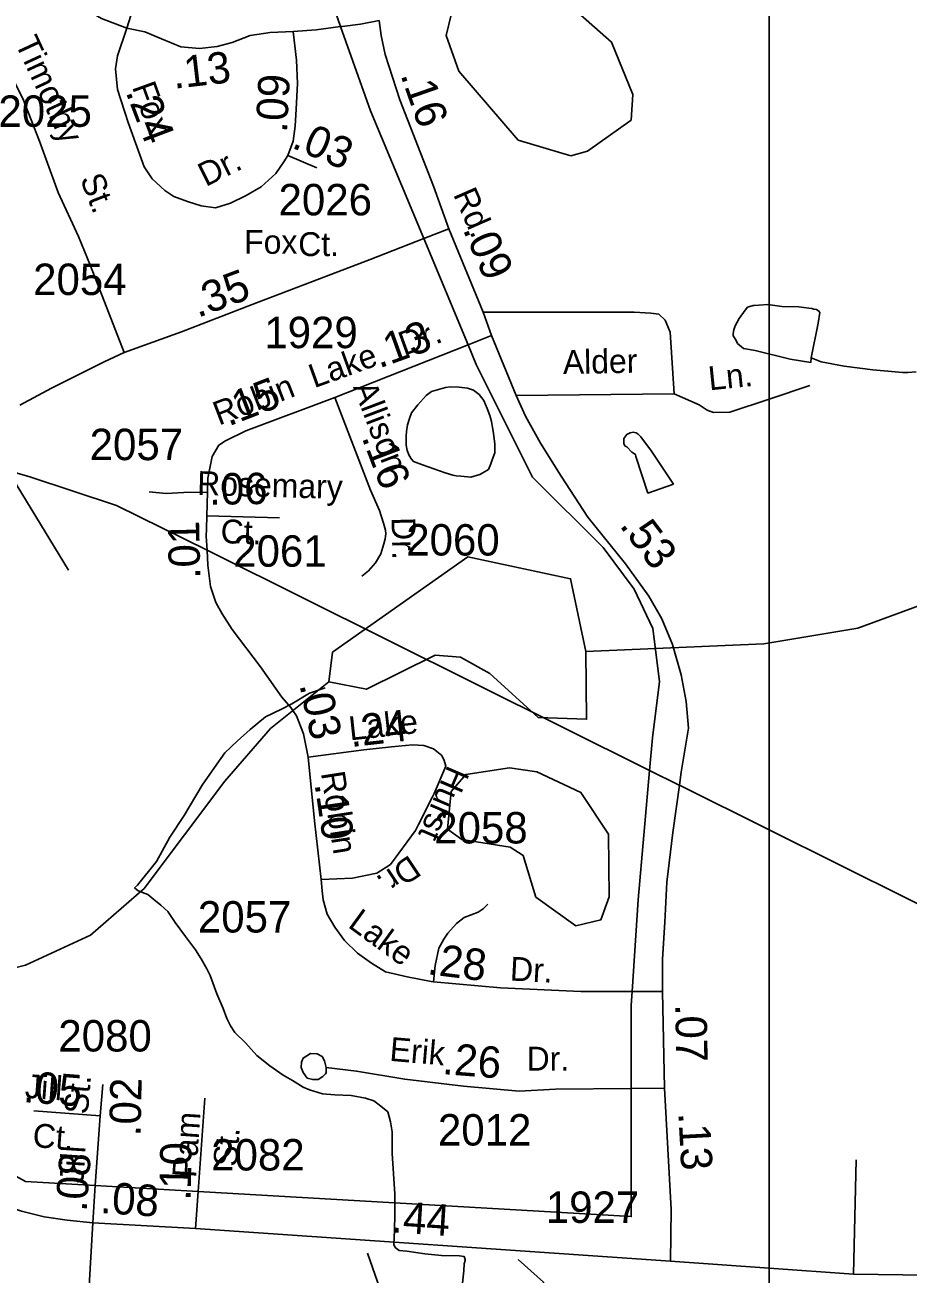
# Model space of a CAD drawing. Extents: x 2206922 to 2357709, y 510027 to 673830.
# Drawn here: x 2293330 to 2296847, y 559014 to 563987 of the extents above; entities that cross this region are included whole.
import ezdxf

# ---------------------------------------------------------------- set-up
doc = ezdxf.new("R2010")
doc.units = 0
for name, color, linetype in [('Exist Boundary Political Urban Extension UEB', 7, 'Continuous'), ('Exist Hydrographic Misc Water Feature', 7, 'Continuous'), ('Exist Hydrographic Pond Under 1500 Sq Ft', 7, 'Continuous'), ('Exist Road Non-System Type 51', 7, 'Continuous'), ('Exist Road Non-System Type 51 Label', 7, 'Continuous'), ('Exist Road Secondary Mileage Hundredths English Label', 7, 'Continuous'), ('Exist Road Secondary Type 51 Attributed', 7, 'Continuous'), ('Exist Road Secondary Type 51 Label', 7, 'Continuous'), ('Exist Road Secondary Type 51 Number Label', 7, 'Continuous'), ('Exist Utilities Electrical Transmission Line', 7, 'Continuous'), ('Map Preparation Inset Cut Line', 7, 'Continuous')]:
    doc.layers.add(name, color=color, linetype=linetype)

msp = doc.modelspace()

# ---------------------------------------------------------------- linework, layer by layer
at = {"layer": 'Exist Boundary Political Urban Extension UEB'}
for p, q in [((2295092.5, 562714.2), (2294916.3, 563137.2)), ((2293609.2, 559370.1), (2294019, 559346.2))]:
    msp.add_line(p, q, dxfattribs=at)
for points in [[(2294584.8, 563980.4), (2294564.4, 564037.5), (2294564.4, 564345.7), (2294555.3, 564400.3)], [(2294916.3, 563137.2), (2294704.6, 563645.2), (2294584.8, 563980.4)], [(2295814.2, 561021.4), (2295825.5, 561151.5), (2295853.5, 561375.6), (2295827, 561586.5), (2295753.2, 561742.1), (2295629.3, 561908), (2295349.1, 562188.2), (2295124.9, 562636.5), (2295092.5, 562714.2)], [(2295745.1, 560141.9), (2295769.5, 560507), (2295814.2, 561021.4)], [(2290079.5, 560836.9), (2290753.2, 560535), (2291902.2, 560226.8), (2292770.9, 559694.4), (2293331.4, 559386.2), (2293609.2, 559370.1)], [(2295741.4, 559756.1), (2295741.4, 560086.7), (2295745.1, 560141.9)], [(2294019, 559346.2), (2295741.4, 559246.1), (2295741.4, 559756.1)]]:
    msp.add_lwpolyline(points, dxfattribs=at)
at = {"layer": 'Exist Hydrographic Misc Water Feature'}
for points in [[(2296458, 562662.8), (2296456.4, 562644.8), (2296374, 562658), (2296233.9, 562692.4), (2296188, 562700.2), (2296180.2, 562706.2), (2296164.2, 562720), (2296157.6, 562734), (2296147.4, 562749.7), (2296147.4, 562759.8), (2296149.2, 562773.7), (2296155, 562789.9), (2296171, 562819.9), (2296194.8, 562852.1), (2296204.4, 562864.4), (2296226.5, 562870.4), (2296230.4, 562870.6), (2296248.7, 562872.7), (2296284.4, 562875), (2296340.6, 562867.4), (2296408.2, 562866.1), (2296448.6, 562860.5), (2296460.5, 562858.6), (2296468.3, 562856.7), (2296478.6, 562854.7), (2296488.2, 562848.8), (2296492.3, 562842.9), (2296484.9, 562801.1), (2296458, 562662.8)], [(2296458, 562662.8), (2296496.8, 562647.2), (2296588.3, 562630.2), (2296702.7, 562615), (2296776.7, 562607.9), (2296820.8, 562604.1), (2296842.5, 562604.5), (2296874.7, 562606.5)], [(2295185.5, 562409.2), (2295189.6, 562385), (2295193.5, 562362.9), (2295195.7, 562341.1), (2295198.4, 562321.2), (2295198.4, 562285.2), (2295188.6, 562257), (2295182.8, 562240.8), (2295173.4, 562218.8), (2295151.5, 562204.6), (2295139.8, 562198.7), (2295103.7, 562188.3), (2295063.5, 562191.9), (2295045.4, 562193.8), (2295031.3, 562195.6), (2295001.6, 562205.3), (2294910.9, 562236.4), (2294875, 562249.9), (2294866.8, 562260), (2294858.6, 562273.9), (2294850.4, 562293.8), (2294846.5, 562315.8), (2294846.1, 562351.6), (2294847.8, 562369.9), (2294851.7, 562395.7), (2294859.5, 562421.8), (2294867.5, 562444.1), (2294892.7, 562476.4), (2294926.3, 562512.6), (2294946.4, 562528.7), (2294974.3, 562537.1), (2295002.4, 562545), (2295022.3, 562547.3), (2295056.5, 562545.8), (2295090.1, 562541.9), (2295113.9, 562534.2), (2295136.5, 562516.3), (2295154.7, 562492.5), (2295168.9, 562460.7), (2295179.1, 562432.8), (2295185.5, 562409.2)], [(2295560.9, 561493.9), (2296269, 561525.5), (2296643, 561586.8), (2297108.1, 561757.8), (2298484, 562402.3)], [(2295909.3, 562159.8), (2295808, 562124.8), (2295760.3, 562270.2), (2295758.2, 562278.3), (2295744.3, 562288.1), (2295724.2, 562308.2), (2295718, 562311.9), (2295712.1, 562320.1), (2295711.9, 562325.8), (2295711.5, 562332), (2295711.5, 562342.1), (2295723.5, 562358.1), (2295737.3, 562364.2), (2295749.6, 562366.4), (2295761.7, 562364.6), (2295769.5, 562358.5), (2295779.3, 562348.5), (2295822, 562291), (2295909.3, 562159.8)], [(2293024.9, 560171.1), (2293332, 560246.8), (2293590, 560366.2), (2293804.1, 560552.1), (2294125, 560978.5), (2294306, 561188), (2294537.9, 561373.5)], [(2293765.7, 560554.4), (2293777.6, 560564.8), (2293852.9, 560659.3), (2293906, 560755.9), (2293962.8, 560842.3), (2294033.9, 560962.9), (2294082.9, 561033.4), (2294124.6, 561091.6), (2294174, 561138.1), (2294225.4, 561184.7), (2294287, 561235), (2294350.7, 561265.6), (2294390.7, 561285.9), (2294462.1, 561328.7), (2294523.6, 561349.5)], [(2295069.6, 558981.7), (2295075.2, 559030), (2295076.8, 559057.7), (2295080.9, 559071.7), (2295080.7, 559075.8), (2295076.8, 559087.7), (2295058.8, 559089.6), (2294986.8, 559091.2), (2294920.8, 559098.2), (2294848.8, 559107.9), (2294818.5, 559111.6), (2294802.7, 559123.4), (2294796.5, 559135.2), (2294799.8, 559191.1), (2294801.2, 559255.4), (2294800.4, 559337), (2294790.8, 559497), (2294790.4, 559583), (2294784.2, 559622.9), (2294773.3, 559662.6), (2294739.3, 559690.5), (2294717.2, 559706), (2294684.8, 559717.8), (2294626.7, 559727.3), (2294562.8, 559730.8), (2294512.7, 559734.3), (2294461, 559749.8), (2294436.6, 559761.6), (2294394.4, 559787), (2294356.5, 559808.5), (2294304, 559846), (2294251.9, 559887.5), (2294207, 559937.3), (2294164.9, 559978.9), (2294146.9, 560004.7), (2294132.6, 560034.5), (2294118, 560074.3), (2294093.2, 560132.1), (2294066.7, 560205.8), (2294052.4, 560231.5), (2294030, 560271.3), (2294008.1, 560307.1), (2293967.7, 560360.6), (2293926.7, 560416.2), (2293898.2, 560459.8), (2293870.3, 560485.6), (2293842, 560507.3), (2293818, 560527.1), (2293779.5, 560542.6), (2293765.7, 560554.4)]]:
    msp.add_lwpolyline(points, dxfattribs=at)
at = {"layer": 'Exist Hydrographic Pond Under 1500 Sq Ft'}
for points in [[(2295501.1, 563466.1), (2295291.9, 563529.4), (2295055.9, 563803), (2295005, 563945.1), (2295045, 564111.5), (2295177.9, 564187.5), (2295394, 564156.9), (2295663.1, 563918.7), (2295748, 563710.3), (2295741, 563608.8), (2295566.9, 563484.4), (2295501.1, 563466.1)], [(2294537.9, 561373.5), (2294552.9, 561491.3), (2295091, 561870.7), (2295500, 561783.8), (2295560.9, 561493.9)], [(2294537.9, 561373.5), (2294688, 561344.3), (2294962, 561479.8), (2295062.1, 561471.2), (2295178.9, 561406.5), (2295371.9, 561232.1), (2295564, 561224.9), (2295560.9, 561493.9)], [(2295521, 560402.7), (2295621, 560426.9), (2295654, 560518.1), (2295651, 560767.3), (2295541.1, 560933.5), (2295365.9, 561015.7), (2295257.1, 561031.1), (2295083, 561005.1), (2295024.9, 560937.4), (2295010, 560786.9), (2295068, 560746.3), (2295259.9, 560716.2), (2295311, 560682.4), (2295362, 560517.4), (2295521, 560402.7)], [(2295291.9, 559075.8), (2295393, 558985.2), (2295396.1, 558709.7), (2295255, 558624), (2295172, 558622.4), (2294963, 558695.5), (2294761, 558902.9), (2294691.9, 559101.1)]]:
    msp.add_lwpolyline(points, dxfattribs=at)
at = {"layer": 'Exist Road Non-System Type 51'}
for p, q in [((2296290.5, 562498.7), (2296451.5, 562552.3)), ((2295283.7, 562513.1), (2295912.3, 562519.2)), ((2293261.5, 562214.6), (2293502.8, 561818.4)), ((2296625.4, 559016.5), (2296636.4, 559471.8))]:
    msp.add_line(p, q, dxfattribs=at)
for points in [[(2293724.4, 562684.5), (2293590.1, 563028.5), (2293543.1, 563145.4), (2293461.1, 563320.1), (2293387.3, 563524.3), (2293321.5, 563695), (2293219.5, 563892.6)], [(2295152.1, 562844.4), (2295753.1, 562843.8), (2295819.2, 562840.4), (2295851.1, 562836.6), (2295876, 562812.1), (2295895.8, 562765.1), (2295912.3, 562519.2)], [(2295912.3, 562519.2), (2296011.6, 562476.2), (2296043.9, 562454.7), (2296069.4, 562445.3), (2296133.9, 562446.6), (2296290.5, 562498.7)], [(2294056.1, 562128.8), (2293962.1, 562126.8), (2293890.9, 562122.7), (2293823.8, 562129.5)], [(2294395.5, 561259.3), (2294387.2, 561272.1), (2294351.6, 561313.1), (2294267, 561434), (2294154.2, 561581.9), (2294113.9, 561643.7), (2294088.4, 561689.4), (2294068.2, 561752.5), (2294057.5, 561837.2), (2294053.8, 561897.9)], [(2294955.3, 560180.7), (2294961.4, 560245.1), (2294975.5, 560313.6), (2294995.6, 560349.9), (2295011.7, 560374.1), (2295046, 560412.4), (2295076.2, 560436.6), (2295132.6, 560456.7), (2295152.7, 560470.9), (2295170.9, 560489)], [(2294524.8, 559814.4), (2294514.5, 559803.8), (2294496.5, 559791.5), (2294474.5, 559791.4), (2294452.6, 559797.2), (2294436.3, 559819), (2294428.1, 559838.9), (2294429.9, 559860.9), (2294435.8, 559876.9), (2294465.6, 559895.1), (2294491.5, 559893.4), (2294511.7, 559883.6), (2294521.8, 559865.8), (2294528, 559839.9)], [(2294528, 559839.9), (2294528.2, 559817.9), (2294524.8, 559814.4)]]:
    msp.add_lwpolyline(points, dxfattribs=at)
at = {"layer": 'Exist Road Secondary Type 51 Attributed'}
for p, q in [((2294375.7, 563468.4), (2294490.9, 563418.5)), ((2295874, 559757.3), (2295865.9, 560142.3)), ((2293628.3, 559647.6), (2293639.2, 559771.5)), ((2293628.3, 559647.6), (2293364.5, 559667)), ((2294008.4, 559198.9), (2293599, 559221.6)), ((2295898.2, 559068.9), (2294008.4, 559198.9))]:
    msp.add_line(p, q, dxfattribs=at)
for points in [[(2293735.3, 563974.6), (2293767.2, 564074.8), (2293803.8, 564120.9), (2293856.3, 564164.4), (2293909, 564201.5), (2293986.7, 564249.2), (2294100.4, 564304.8), (2294252.9, 564368.4), (2294316.4, 564391.7), (2294352.2, 564400.3), (2294435, 564402.3), (2294555.3, 564400.3), (2294589.3, 564399.7), (2294718.3, 564395)], [(2293735.3, 563974.6), (2293634.5, 564012.4), (2293551.9, 564061.1), (2293497, 564128.5), (2293463.2, 564203.9), (2293416.4, 564251.8), (2293359.8, 564283.1)], [(2294375.7, 563468.4), (2294358.8, 563442.4), (2294327, 563395.8), (2294268.6, 563343), (2294209.6, 563308.9), (2294147.2, 563277.8), (2294087.7, 563259.5), (2294030.6, 563267), (2293976.3, 563284.1), (2293922, 563304.4), (2293886.5, 563328), (2293835.7, 563374.6), (2293803.9, 563423.3), (2293740.4, 563599.2), (2293698, 563730.4), (2293689.6, 563813.2), (2293697.4, 563864.5), (2293735.3, 563974.6)], [(2294396.4, 563961.2), (2294304.8, 563957.7), (2294226.1, 563945.2), (2294154.2, 563916.9), (2294094.6, 563901.9), (2294024.2, 563893.7), (2293949.3, 563899.6), (2293872.5, 563931.8), (2293806, 563959.4), (2293735.3, 563974.6)], [(2294738.4, 564005.3), (2294664.3, 563990.4), (2294591.8, 563981.3), (2294584.8, 563980.4), (2294487.9, 563967.8), (2294396.4, 563961.2)], [(2295016.4, 563176.3), (2294955.3, 563345.1), (2294821.3, 563689.1), (2294762.7, 563870.1), (2294746.3, 563944.6), (2294738.4, 564005.3)], [(2294396.4, 563961.2), (2294409.2, 563846.7), (2294413.8, 563753.9), (2294408.4, 563651.8), (2294404, 563584.5), (2294396.9, 563525.1), (2294375.7, 563468.4)], [(2293309.4, 562474.2), (2293435.6, 562542.7), (2293645.1, 562646.2), (2293724.4, 562684.5), (2293952.7, 562766.4), (2294233.4, 562875.3), (2294703.5, 563054), (2294916.3, 563137.2), (2295016.4, 563176.3)], [(2295185.7, 562751), (2295152.1, 562844.4), (2295016.4, 563176.3)], [(2295185.7, 562751), (2295092.5, 562714.2), (2294562.5, 562505.1)], [(2295865.9, 560142.3), (2295865.4, 560270.2), (2295875.5, 560417), (2295882.7, 560576), (2295906.6, 560774.2), (2295932.9, 560962.3), (2295940.2, 561014.5), (2295968.7, 561188.8), (2295960.6, 561295), (2295940.5, 561401.1), (2295905.5, 561522.1), (2295863.9, 561624.2), (2295811.5, 561714.2), (2295718.9, 561843.2), (2295568.4, 562028.7), (2295462.3, 562191.3), (2295380.4, 562323), (2295321.3, 562430.5), (2295283.7, 562513.1), (2295185.7, 562751)], [(2294562.5, 562505.1), (2294207.9, 562372), (2294126.8, 562332.6), (2294101.2, 562315.6), (2294073.6, 562269.9), (2294057.5, 562184.6), (2294056.1, 562128.8), (2294053.4, 562034.7)], [(2294562.5, 562505.1), (2294704.8, 562136.9), (2294739.8, 562054.9), (2294755.9, 562005.2), (2294763.2, 561976.6), (2294764.9, 561962.3), (2294762.6, 561942), (2294757.2, 561923.2), (2294745.8, 561883.4), (2294724.2, 561847.8), (2294696.2, 561814.7), (2294669.5, 561794.4)], [(2294053.4, 562034.7), (2294051.5, 561982), (2294050.5, 561953.4), (2294053.8, 561897.9)], [(2294053.4, 562034.7), (2294342.2, 562026.7)], [(2294455.7, 561074.6), (2294437.6, 561167.3), (2294409.4, 561237.8), (2294395.5, 561259.3)], [(2294455.7, 561074.6), (2294677.3, 561102.8), (2294788.1, 561114.9), (2294870.7, 561122.9), (2294917, 561120.9), (2294955.3, 561106.8), (2294987.5, 561080.6), (2294997.6, 561060.5), (2295003.7, 561038.3), (2294957.3, 560929.4), (2294950.7, 560916.3)], [(2294508.1, 560586.8), (2294481.9, 560820.6), (2294455.7, 561074.6)], [(2294950.7, 560916.3), (2294894.9, 560806.5), (2294882.8, 560782.3), (2294784.1, 560647.2), (2294729.7, 560613), (2294633, 560592.8), (2294508.1, 560586.8)], [(2293599, 559221.6), (2293496.8, 559232.4), (2293406.1, 559245.3), (2293315.4, 559267.5), (2293218.7, 559299.7), (2293041.4, 559394.5), (2292791.1, 559525.1), (2292504.6, 559688.9), (2292129.1, 559890.9), (2291851.9, 560034.6), (2291737.4, 560081.4), (2291582.9, 560142), (2291334.2, 560229.5), (2290744.7, 560432), (2289908, 560741.5)], [(2295865.9, 560142.3), (2295745.1, 560141.9), (2295541.6, 560141.3), (2295221.2, 560156.4), (2294955.3, 560180.7), (2294945.2, 560181.6), (2294850.6, 560199.7), (2294763.9, 560219.9), (2294707.5, 560254.2), (2294653.1, 560294.5), (2294600.7, 560344.9), (2294562.5, 560397.3), (2294532.2, 560449.7), (2294516.1, 560506.1), (2294512.1, 560542.4), (2294508.1, 560586.8)], [(2295874, 559757.3), (2295741.4, 559756.1), (2295440.8, 559753.3), (2295295.8, 559745.2), (2295074.2, 559765.4), (2294840.5, 559792.6), (2294649.1, 559824.8), (2294528, 559839.9)], [(2295898.2, 559068.9), (2295900.2, 559274.5), (2295874, 559757.3)], [(2294008.4, 559198.9), (2294019, 559346.2), (2294045.6, 559717.3)], [(2293599, 559221.6), (2293609.2, 559370.1), (2293628.3, 559647.6)], [(2293599, 559221.6), (2293571, 558742)], [(2298859.7, 558470.4), (2298505, 558600.3), (2298291.2, 558676.4), (2297727.2, 558892.3), (2297482.7, 558970), (2297362.4, 558994.9), (2297214.4, 559009.5), (2296625.4, 559016.5), (2296290.5, 559040.6), (2295898.2, 559068.9)]]:
    msp.add_lwpolyline(points, dxfattribs=at)
at = {"layer": 'Exist Utilities Electrical Transmission Line'}
msp.add_line((2295932.9, 560962.3), (2296290.5, 560784.4), dxfattribs=at)
for points in [[(2293261.5, 562214.6), (2293348.6, 562189.4), (2293693.6, 562074.7), (2294053.8, 561897.9)], [(2294053.8, 561897.9), (2294081.2, 561884.5), (2295814.2, 561021.4)], [(2295814.2, 561021.4), (2295932.8, 560962.4), (2295932.9, 560962.3)], [(2296290.5, 560784.4), (2298507.6, 559681.3), (2299341.4, 559256.6)]]:
    msp.add_lwpolyline(points, dxfattribs=at)
at = {"layer": 'Map Preparation Inset Cut Line'}
for p, q in [((2296290.5, 564742.9), (2296290.5, 562498.7)), ((2296290.5, 562498.7), (2296290.5, 560784.4)), ((2296290.5, 560784.4), (2296290.5, 559040.6)), ((2296290.5, 559040.6), (2296290.5, 556643.1))]:
    msp.add_line(p, q, dxfattribs=at)

# ---------------------------------------------------------------- texts
at = {"layer": 'Exist Road Non-System Type 51 Label'}
for s, rotation, p in [('Timothy', 294.9543, (2293288.2, 563916.2)), ('St.', 291.342, (2293547.5, 563374.7)), ('Alder', 1.1146, (2295470.2, 562597.9)), ('Ln.', 5.8419, (2296052.7, 562533.2)), ('Jill', 355.7903, (2293327.4, 559719.1)), ('St.', 84.9728, (2293579.2, 559651.1)), ('Pam', 85.983, (2294010.1, 559398.6)), ('Ct.', 355.7903, (2293357.6, 559522.9)), ('St.', 85.983, (2294173.4, 559443)), ('Jill', 86.2873, (2293561.5, 559377.2))]:
    msp.add_text(s, height=95, rotation=rotation, dxfattribs=at).set_placement(p)
at = {"layer": 'Exist Road Secondary Mileage Hundredths English Label'}
for s, rotation, p in [('.13', 6.5815, (2293922.6, 563733)), ('.09', 86.9683, (2294371.7, 563556.6)), ('.16', 289.2316, (2294822.4, 563788.9)), ('.24', 290.84, (2293728.9, 563721.1)), ('.03', 336.5606, (2294386.1, 563500.6)), ('.09', 293.502, (2295070, 563174.2)), ('.35', 20.4497, (2294017.1, 562821.1)), ('.13', 19.825, (2294738.5, 562619.9)), ('.15', 21.1282, (2294139.1, 562389.2)), ('.16', 290.7627, (2294668.1, 562346.6)), ('.06', 0.7733, (2294062.8, 562078.1)), ('.01', 91.2538, (2294027.3, 561783.4)), ('.53', 307.3215, (2295692, 561995.4)), ('.03', 282.1714, (2294421.1, 561362.2)), ('.24', 6.4889, (2294626.6, 561114)), ('.10', 278.4184, (2294481.4, 560967)), ('.28', 353.032, (2294927.1, 560210.8)), ('.07', 271.1991, (2295916.2, 560091.4)), ('.26', 355.5906, (2294987.6, 559813.3)), ('.05', 355.5906, (2293320.2, 559701.9)), ('.02', 88.8611, (2293789.5, 559564.9)), ('.13', 273.1053, (2295928.6, 559658.9)), ('.08', 85.5906, (2293574.4, 559263.5)), ('.10', 88.8611, (2293988.4, 559308.6)), ('.08', 356.3118, (2293626.8, 559260.5)), ('.44', 356.3118, (2294784.4, 559183.6))]:
    msp.add_text(s, height=125, rotation=rotation, dxfattribs=at).set_placement(p)
at = {"layer": 'Exist Road Secondary Type 51 Label'}
for s, rotation, p in [('Fox', 289.8609, (2293754.4, 563741)), ('Dr.', 26.5159, (2294048.9, 563341.8)), ('Rd.', 293.6471, (2295032, 563313.3)), ('Dr.', 19.825, (2294837.1, 562670.2)), ('Lake', 19.825, (2294480, 562541.4)), ('Robin', 21.1282, (2294100.9, 562392.7)), ('Allison', 290.7627, (2294633.8, 562547.3)), ('Rosemary', 358.3467, (2294013.6, 562117.4)), ('Ct.', 358.3467, (2294106.9, 561925.4)), ('Dr.', 271.5002, (2294787.6, 562027.7)), ('Lake', 6.2838, (2294622.9, 561140.4)), ('Hurst', 246.8249, (2295012.5, 561045.9)), ('Robin', 278.9022, (2294506.7, 561011.2)), ('Dr.', 213.9407, (2294860.2, 560687.6)), ('Lake', 324.0154, (2294610.3, 560400.2)), ('Dr.', 357.0165, (2295257.4, 560185.4)), ('Erik', 355.0949, (2294777.7, 559866.1)), ('Dr.', 0.089, (2295325.3, 559826.8))]:
    msp.add_text(s, height=95, rotation=rotation, dxfattribs=at).set_placement(p)
for s, p in [('Fox', (2294201.6, 563076.6)), ('Ct.', (2294416.7, 563067.6))]:
    msp.add_text(s, height=95, dxfattribs=at).set_placement(p)
at = {"layer": 'Exist Road Secondary Type 51 Number Label'}
for s, p in [('2025', (2293223.9, 563581.8)), ('2026', (2294338.3, 563229.6)), ('2054', (2293362, 562912.7)), ('1929', (2294281.7, 562701.2)), ('2057', (2293586.8, 562255.7)), ('2060', (2294846.4, 561876.1)), ('2061', (2294158, 561831.7)), ('2058', (2294957.6, 560730.6)), ('2057', (2294017.4, 560376.2)), ('2080', (2293462.3, 559902.9)), ('2012', (2294972.5, 559528.8)), ('2082', (2294070.4, 559429.5)), ('1927', (2295401.6, 559221))]:
    msp.add_text(s, height=125, dxfattribs=at).set_placement(p)

doc.saveas('drawing.dxf')
